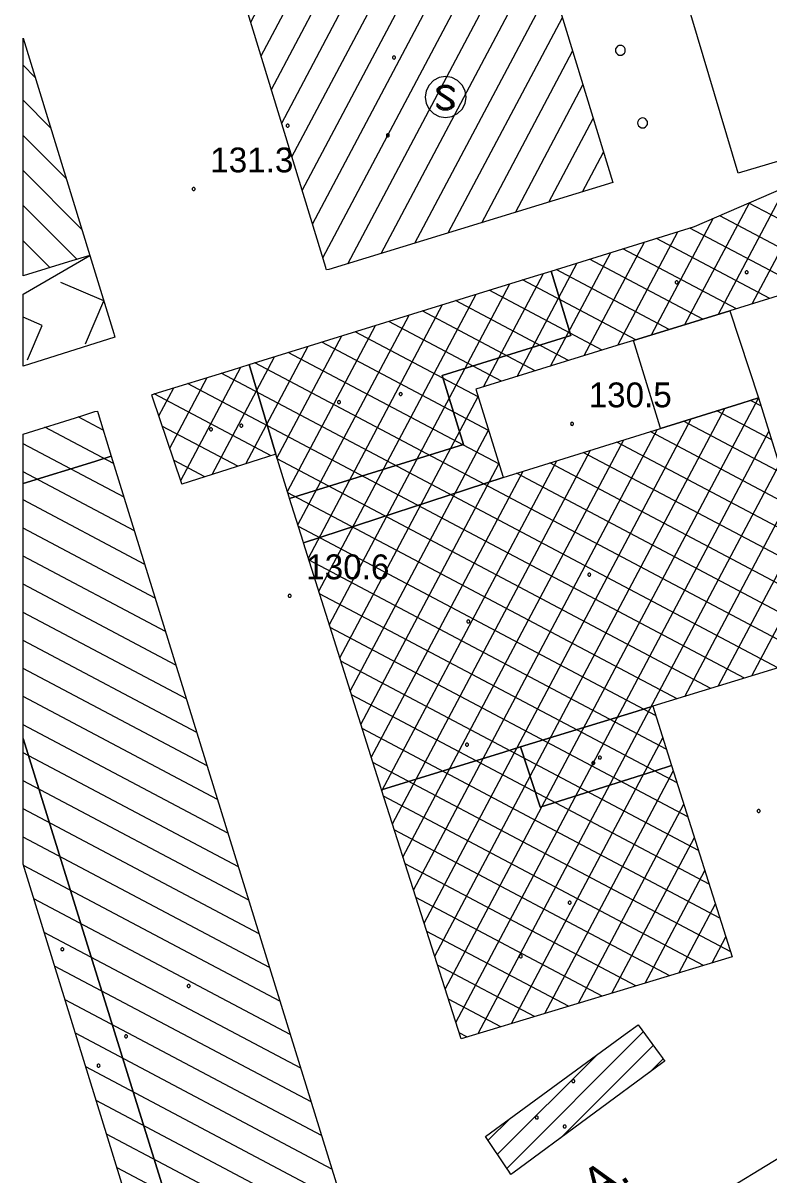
# Model space of a CAD drawing. Extents: x 513373 to 514978, y 5038576 to 5040180.
# Drawn here: x 513373 to 513418.1, y 5038650.3 to 5038719.9 of the extents above; entities that cross this region are included whole.
import ezdxf

# ---------------------------------------------------------------- set-up
doc = ezdxf.new("R2010")
doc.units = 0
for name, color, linetype in [('2010300', 7, 'Continuous'), ('3030201', 7, 'Continuous'), ('3060104', 7, 'Continuous'), ('3090300', 7, 'Continuous'), ('C1131', 7, 'Continuous'), ('C12211', 7, 'Continuous'), ('C1228', 7, 'Continuous'), ('C211113', 7, 'Continuous'), ('C21159', 7, 'Continuous'), ('C21195', 7, 'Continuous'), ('CAMP_C12211', 7, 'Continuous'), ('CAMP_C1228', 7, 'Continuous'), ('CAMP_C21195', 7, 'Continuous'), ('Default', 7, 'Continuous'), ('F12107', 7, 'Continuous'), ('F12131', 7, 'Continuous'), ('F12132', 7, 'Continuous'), ('G4315', 7, 'Continuous'), ('TOP500', 7, 'Continuous'), ('TOP920', 7, 'Continuous')]:
    doc.layers.add(name, color=color, linetype=linetype)

# ---------------------------------------------------------------- blocks, each defined once
blk = doc.blocks.new('CAMP_3A5802B0')
at = {"layer": 'CAMP_C12211'}
for p, q in [((-2.527, 26.797), (-4.04, 27.598)), ((-1.899, 24.767), (-6.054, 26.968)), ((-1.271, 22.738), (-7.369, 25.967)), ((-0.644, 20.708), (-7.369, 24.269)), ((-0.016, 18.679), (-7.369, 22.572)), ((0.612, 16.649), (-7.369, 20.875)), ((1.24, 14.619), (-7.369, 19.177)), ((1.867, 12.59), (-7.369, 17.48)), ((2.495, 10.56), (-7.369, 15.783)), ((3.123, 8.53), (-7.369, 14.086)), ((3.75, 6.501), (-7.369, 12.388)), ((4.378, 4.471), (-7.369, 10.691)), ((5.006, 2.441), (-7.369, 8.994)), ((5.634, 0.412), (-7.37, 7.297)), ((6.261, -1.618), (-7.37, 5.599)), ((6.889, -3.648), (-7.37, 3.902)), ((7.517, -5.677), (-7.37, 2.205)), ((8.144, -7.707), (-7.345, 0.494)), ((8.772, -9.736), (-6.717, -1.535)), ((9.4, -11.766), (-6.089, -3.565)), ((10.028, -13.796), (-5.461, -5.595)), ((10.655, -15.825), (-4.833, -7.625)), ((11.283, -17.855), (-4.206, -9.654)), ((11.911, -19.885), (-3.578, -11.684)), ((12.539, -21.914), (-2.95, -13.714)), ((11.923, -23.286), (-2.322, -15.743)), ((9.9, -23.912), (-1.695, -17.773)), ((7.876, -24.538), (-1.067, -19.803)), ((5.853, -25.164), (-0.439, -21.832)), ((3.829, -25.79), (0.188, -23.862)), ((1.806, -26.415), (0.816, -25.891))]:
    blk.add_line(p, q, dxfattribs=at)
blk = doc.blocks.new('CAMP_540BAC70')
at = {"layer": 'CAMP_C1228'}
for p, q in [((8.768, 14.056), (13.188, 22.405)), ((14.521, 22.096), (13.601, 22.584)), ((10.76, 14.613), (14.596, 21.858)), ((15.156, 20.063), (11.837, 21.82)), ((6.74, 13.431), (10.986, 21.452)), ((15.792, 18.029), (10.073, 21.057)), ((4.712, 12.807), (8.784, 20.499)), ((16.427, 15.996), (8.31, 20.293)), ((2.684, 12.182), (6.582, 19.545)), ((17.062, 13.962), (6.546, 19.53)), ((11.386, 12.589), (15.226, 19.842)), ((0.656, 11.558), (4.38, 18.592)), ((17.697, 11.928), (4.783, 18.766)), ((-1.372, 10.933), (2.262, 17.798)), ((9.846, 14.388), (2.984, 18.021)), ((12.011, 10.565), (15.855, 17.825)), ((-3.401, 10.307), (0.232, 17.168)), ((5.793, 13.14), (-1.06, 16.768)), ((7.819, 13.764), (0.962, 17.395)), ((-5.429, 9.682), (-1.799, 16.539)), ((3.766, 12.515), (-3.081, 16.141)), ((-7.457, 9.057), (-3.829, 15.909)), ((1.739, 11.891), (-5.103, 15.514)), ((12.637, 8.541), (16.485, 15.809)), ((-18.794, -5.942), (-7.891, 14.65)), ((-9.486, 8.432), (-5.86, 15.279)), ((-0.288, 11.267), (-7.125, 14.887)), ((-19.426, -3.932), (-9.921, 14.02)), ((-2.314, 10.643), (-9.146, 14.26)), ((-20.059, -1.922), (-11.952, 13.39)), ((-4.34, 10.018), (-11.168, 13.633)), ((18.332, 9.895), (11.022, 13.765)), ((13.263, 6.518), (17.115, 13.793)), ((-20.692, 0.089), (-13.983, 12.761)), ((-6.366, 9.393), (-13.19, 13.007)), ((-21.325, 2.099), (-16.014, 12.131)), ((-8.392, 8.769), (-15.211, 12.38)), ((-21.958, 4.109), (-18.044, 11.501)), ((-9.799, 7.817), (-17.233, 11.753)), ((18.967, 7.861), (11.649, 11.736)), ((13.889, 4.494), (17.745, 11.777)), ((-23.83, 3.779), (-20.075, 10.872)), ((-8.55, 3.761), (-21.276, 10.499)), ((-9.175, 5.789), (-19.255, 11.126)), ((-25.872, 3.129), (-22.106, 10.242)), ((10.329, -7.932), (-23.298, 9.872)), ((14.514, 2.47), (18.374, 9.76)), ((-27.767, 2.755), (-24.136, 9.614)), ((8.3, -8.556), (-25.324, 9.248)), ((19.603, 5.828), (12.277, 9.706)), ((-29.088, 6.671), (-28.191, 8.365)), ((-28.427, 4.713), (-26.163, 8.989)), ((6.272, -9.179), (-27.351, 8.624)), ((-22.316, 4.261), (-29.378, 8)), ((-18.161, -7.952), (-9.804, 7.831)), ((-11.793, -27.982), (7.121, 7.74)), ((20.238, 3.794), (12.904, 7.677)), ((15.14, 0.446), (19.004, 7.744)), ((-12.432, -25.984), (5.096, 7.121)), ((7.9, 5.235), (4.618, 6.972)), ((7.268, 7.267), (6.637, 7.6)), ((-13.072, -23.986), (3.064, 6.489)), ((8.531, 3.203), (2.598, 6.344)), ((-24.319, 3.623), (-28.873, 6.035)), ((-17.528, -9.962), (-9.179, 5.805)), ((-13.711, -21.987), (1.032, 5.857)), ((-11.154, -29.981), (7.749, 5.72)), ((9.163, 1.171), (0.579, 5.716)), ((20.873, 1.76), (13.532, 5.647)), ((15.766, -1.577), (19.634, 5.728)), ((-14.35, -19.989), (-1, 5.225)), ((9.795, -0.86), (-1.441, 5.088)), ((-14.989, -17.991), (-3.031, 4.594)), ((10.427, -2.892), (-3.46, 4.46)), ((-26.321, 2.986), (-28.176, 3.969)), ((4.244, -9.802), (-21.944, 4.063)), ((-16.895, -11.973), (-8.555, 3.778)), ((-15.629, -15.993), (-5.063, 3.962)), ((-9.815, -30.657), (8.377, 3.701)), ((11.058, -4.924), (-5.48, 3.832)), ((21.508, -0.273), (14.159, 3.618)), ((16.392, -3.601), (20.264, 3.712)), ((-16.262, -13.983), (-7.095, 3.33)), ((11.69, -6.956), (-7.499, 3.204)), ((2.215, -10.426), (-21.303, 2.027)), ((2.668, -10.286), (9.005, 1.681)), ((22.143, -2.307), (14.787, 1.588)), ((17.017, -5.625), (20.893, 1.696)), ((0.908, -11.431), (-20.661, -0.01)), ((4.695, -9.664), (9.633, -0.339)), ((22.779, -4.34), (15.415, -0.441)), ((17.643, -7.649), (21.523, -0.321)), ((1.557, -13.471), (-20.02, -2.047)), ((6.722, -9.041), (10.26, -2.358)), ((23.414, -6.374), (16.042, -2.471)), ((18.269, -9.672), (22.153, -2.337)), ((2.205, -15.512), (-19.379, -4.084)), ((8.75, -8.418), (10.888, -4.378)), ((23.709, -8.227), (16.67, -4.5)), ((20.138, -9.347), (22.783, -4.353)), ((2.853, -17.552), (-18.737, -6.121)), ((10.777, -7.795), (11.516, -6.397)), ((21.695, -8.859), (17.297, -6.53)), ((22.174, -8.709), (23.412, -6.369)), ((3.501, -19.593), (-18.096, -8.158)), ((19.682, -9.49), (17.925, -8.56)), ((4.15, -21.633), (-17.455, -10.195)), ((4.798, -23.674), (-16.813, -12.231)), ((-7.794, -30.047), (1.341, -12.793)), ((5.446, -25.714), (-16.172, -14.268)), ((-5.774, -29.437), (1.978, -14.796)), ((3.808, -26.544), (-15.528, -16.306)), ((-3.754, -28.827), (2.614, -16.8)), ((1.766, -27.16), (-14.875, -18.35)), ((-1.734, -28.217), (3.251, -18.803)), ((-0.276, -27.777), (-14.221, -20.393)), ((0.286, -27.607), (3.887, -20.807)), ((-2.317, -28.393), (-13.567, -22.436)), ((2.307, -26.997), (4.524, -22.81)), ((-4.359, -29.009), (-12.914, -24.48)), ((4.327, -26.387), (5.16, -24.814)), ((-6.4, -29.626), (-12.26, -26.523)), ((-8.442, -30.242), (-11.606, -28.567)), ((-10.483, -30.859), (-10.953, -30.61))]:
    blk.add_line(p, q, dxfattribs=at)
blk = doc.blocks.new('CAMP_E6EC42B5')
at = {"layer": 'CAMP_C12211'}
for p, q in [((-0.396, 5.699), (-1.115, 6.418)), ((0.543, 2.639), (-1.115, 4.297)), ((1.482, -0.422), (-1.115, 2.176)), ((2.421, -3.482), (-1.115, 0.054)), ((2.131, -5.313), (-1.115, -2.067)), ((0.508, -5.811), (-1.115, -4.188))]:
    blk.add_line(p, q, dxfattribs=at)
blk = doc.blocks.new('CAMP_7295D72C')
at = {"layer": 'CAMP_C12211'}
for p, q in [((15.402, 5.835), (27.505, 28.695)), ((11.114, 0.944), (25.534, 28.177)), ((9.09, 0.327), (23.51, 27.56)), ((7.067, -0.29), (21.486, 26.943)), ((17.426, 6.452), (28.125, 26.661)), ((15.419, 18.691), (19.462, 26.326)), ((14.179, 22.76), (15.414, 25.093)), ((14.799, 20.725), (17.438, 25.71)), ((18.998, 6.217), (28.745, 24.626)), ((19.619, 4.183), (29.366, 22.592)), ((20.239, 2.149), (29.986, 20.557)), ((20.992, 0.365), (30.606, 18.523)), ((5.043, -0.907), (14.588, 17.121)), ((3.019, -1.524), (12.564, 16.504)), ((23.016, 0.982), (31.226, 16.488)), ((1.275, -1.612), (10.54, 15.887)), ((-17.372, -7.98), (-5.338, 14.749)), ((-0.945, 0.606), (6.492, 14.653)), ((0.651, 0.415), (8.516, 15.27)), ((-19.388, -8.582), (-7.363, 14.13)), ((-15.356, -7.378), (-3.717, 14.606)), ((-2.961, 0.006), (4.468, 14.036)), ((25.04, 1.599), (31.846, 14.454)), ((-21.404, -9.183), (-9.388, 13.51)), ((-16.459, -22.283), (2.444, 13.419)), ((-23.42, -9.785), (-11.414, 12.891)), ((-13.562, -7.195), (-3.094, 12.575)), ((-12.321, -11.262), (0.42, 12.802)), ((-24.597, -8.802), (-13.439, 12.272)), ((-12.941, -9.228), (-1.603, 12.185)), ((27.064, 2.216), (32.466, 12.419)), ((-25.249, -6.828), (-15.464, 11.652)), ((-27.268, -7.437), (-17.489, 11.033)), ((-31.307, -8.654), (-21.54, 9.794)), ((-29.288, -8.045), (-19.515, 10.413)), ((29.088, 2.833), (33.086, 10.385)), ((-27.723, 1.321), (-23.565, 9.175)), ((-28.349, 3.345), (-25.59, 8.555)), ((-28.974, 5.369), (-27.615, 7.936)), ((31.112, 3.45), (33.706, 8.35)), ((33.136, 4.067), (34.326, 6.316)), ((13.138, 1.561), (14.823, 4.742)), ((15.162, 2.178), (15.443, 2.708)), ((-32.079, -6.906), (-28.195, 0.43)), ((-32.079, -3.7), (-30.208, -0.167)), ((-5.249, -4.317), (-3.742, -1.471)), ((-3.237, -3.721), (-3.133, -3.526)), ((-15.838, -24.317), (-6.237, -6.182)), ((-15.218, -26.35), (-5.616, -8.215)), ((-14.597, -28.383), (-4.995, -10.248)), ((-17.08, -20.25), (-12.345, -11.308)), ((-17.701, -18.217), (-14.376, -11.939)), ((-13.976, -30.416), (-4.374, -12.281)), ((-12.474, -30.784), (-2.542, -12.026)), ((-10.448, -30.164), (-0.748, -11.844)), ((-18.943, -14.151), (-18.439, -13.2)), ((-18.322, -16.184), (-16.408, -12.569)), ((-8.422, -29.543), (-0.127, -13.877)), ((-6.396, -28.923), (0.494, -15.91)), ((-4.37, -28.302), (1.114, -17.943)), ((-2.345, -27.682), (1.735, -19.976)), ((-0.319, -27.061), (2.356, -22.009)), ((1.707, -26.441), (2.977, -24.043))]:
    blk.add_line(p, q, dxfattribs=at)
blk = doc.blocks.new('CAMP_DF5335D6')
at = {"layer": 'CAMP_C21195'}
for p, q in [((-4.236, -4.236), (4.007, 4.007)), ((-0.991, -2.405), (4.607, 3.193)), ((-4.803, -3.389), (1.235, 2.649)), ((4.389, 1.561), (5.206, 2.378)), ((-5.37, -2.542), (-4.044, -1.215))]:
    blk.add_line(p, q, dxfattribs=at)
blk = doc.blocks.new('08020400')
at = {"layer": 'Default'}
for p, q in [((-0.086, 0.028), (-0.09, 0)), ((-0.09, 0), (-0.086, -0.028)), ((-0.073, 0.053), (-0.086, 0.028)), ((-0.053, 0.073), (-0.073, 0.053)), ((-0.028, 0.086), (-0.053, 0.073)), ((0, 0.09), (-0.028, 0.086)), ((0.028, 0.086), (0, 0.09)), ((0.053, 0.073), (0.028, 0.086)), ((0.073, 0.053), (0.053, 0.073)), ((0.086, 0.028), (0.073, 0.053)), ((0.09, 0), (0.086, 0.028)), ((0.086, -0.028), (0.09, 0)), ((-0.086, -0.028), (-0.073, -0.053)), ((-0.073, -0.053), (-0.053, -0.073)), ((-0.053, -0.073), (-0.028, -0.086)), ((-0.028, -0.086), (0, -0.09)), ((0, -0.09), (0.028, -0.086)), ((0.028, -0.086), (0.053, -0.073)), ((0.053, -0.073), (0.073, -0.053)), ((0.073, -0.053), (0.086, -0.028))]:
    blk.add_line(p, q, dxfattribs=at)
blk = doc.blocks.new('NSIMB25')
at = {"layer": 'Default'}
for p, q in [((-0.086, 0.028), (-0.09, 0)), ((-0.09, 0), (-0.086, -0.028)), ((-0.073, 0.053), (-0.086, 0.028)), ((-0.053, 0.073), (-0.073, 0.053)), ((-0.028, 0.086), (-0.053, 0.073)), ((0, 0.09), (-0.028, 0.086)), ((0.028, 0.086), (0, 0.09)), ((0.053, 0.073), (0.028, 0.086)), ((0.073, 0.053), (0.053, 0.073)), ((0.086, 0.028), (0.073, 0.053)), ((0.09, 0), (0.086, 0.028)), ((0.086, -0.028), (0.09, 0)), ((-0.086, -0.028), (-0.073, -0.053)), ((-0.073, -0.053), (-0.053, -0.073)), ((-0.053, -0.073), (-0.028, -0.086)), ((-0.028, -0.086), (0, -0.09)), ((0, -0.09), (0.028, -0.086)), ((0.028, -0.086), (0.053, -0.073)), ((0.053, -0.073), (0.073, -0.053)), ((0.073, -0.053), (0.086, -0.028))]:
    blk.add_line(p, q, dxfattribs=at)
blk = doc.blocks.new('05010100')
at = {"layer": 'Default'}
for p, q in [((-0.143, 0.046), (-0.15, 0)), ((-0.15, 0), (-0.143, -0.046)), ((-0.121, 0.088), (-0.143, 0.046)), ((-0.088, 0.121), (-0.121, 0.088)), ((-0.046, 0.143), (-0.088, 0.121)), ((0, 0.15), (-0.046, 0.143)), ((0.046, 0.143), (0, 0.15)), ((0.088, 0.121), (0.046, 0.143)), ((0.121, 0.088), (0.088, 0.121)), ((0.143, 0.046), (0.121, 0.088)), ((0.15, 0), (0.143, 0.046)), ((0.143, -0.046), (0.15, 0)), ((-0.143, -0.046), (-0.121, -0.088)), ((-0.121, -0.088), (-0.088, -0.121)), ((-0.088, -0.121), (-0.046, -0.143)), ((-0.046, -0.143), (0, -0.15)), ((0, -0.15), (0.046, -0.143)), ((0.046, -0.143), (0.088, -0.121)), ((0.088, -0.121), (0.121, -0.088)), ((0.121, -0.088), (0.143, -0.046))]:
    blk.add_line(p, q, dxfattribs=at)
blk = doc.blocks.new('03030201')
at = {"layer": 'Default'}
for p, q in [((-1.001, 0.728), (-1.177, 0.382)), ((-0.728, 1.001), (-1.001, 0.728)), ((-0.382, 1.177), (-0.728, 1.001)), ((0, 1.237), (-0.382, 1.177)), ((-0.368, 0.643), (-0.158, 0.718)), ((-0.158, 0.718), (0.127, 0.718)), ((0.382, 1.177), (0, 1.237)), ((0.127, 0.718), (0.337, 0.643)), ((0.728, 1.001), (0.382, 1.177)), ((1.001, 0.728), (0.728, 1.001)), ((1.177, 0.382), (1.001, 0.728)), ((-1.177, 0.382), (-1.238, 0)), ((-1.238, 0), (-1.177, -0.382)), ((-0.518, 0.508), (-0.368, 0.643)), ((-0.518, 0.358), (-0.518, 0.508)), ((-0.443, 0.223), (-0.518, 0.358)), ((-0.333, 0.584), (-0.451, 0.478)), ((-0.451, 0.478), (-0.451, 0.376)), ((-0.451, 0.376), (-0.389, 0.265)), ((-0.368, 0.148), (-0.443, 0.223)), ((-0.389, 0.265), (-0.326, 0.201)), ((-0.298, 0.526), (-0.383, 0.448)), ((-0.383, 0.448), (-0.383, 0.394)), ((-0.383, 0.394), (-0.335, 0.306)), ((0.148, -0.186), (-0.368, 0.148)), ((-0.335, 0.306), (-0.287, 0.257)), ((-0.147, 0.651), (-0.333, 0.584)), ((-0.326, 0.201), (0.183, -0.128)), ((-0.135, 0.583), (-0.298, 0.526)), ((-0.287, 0.257), (-0.18, 0.198)), ((-0.18, 0.198), (0.337, -0.137)), ((0.115, 0.651), (-0.147, 0.651)), ((0.103, 0.583), (-0.135, 0.583)), ((0.266, 0.526), (0.103, 0.583)), ((0.301, 0.584), (0.115, 0.651)), ((0.487, 0.327), (0.266, 0.526)), ((0.487, 0.418), (0.301, 0.584)), ((0.337, 0.643), (0.487, 0.508)), ((0.487, 0.508), (0.487, 0.327)), ((1.238, 0), (1.177, 0.382)), ((1.177, -0.382), (1.238, 0)), ((-1.177, -0.382), (-1.001, -0.728)), ((-0.518, -0.39), (-0.298, -0.588)), ((-0.518, -0.572), (-0.518, -0.39)), ((-0.333, -0.647), (-0.518, -0.481)), ((-0.368, -0.707), (-0.518, -0.572)), ((-0.147, -0.714), (-0.333, -0.647)), ((-0.298, -0.588), (-0.135, -0.647)), ((-0.135, -0.647), (0.103, -0.647)), ((0.103, -0.647), (0.266, -0.588)), ((0.301, -0.647), (0.115, -0.714)), ((0.254, -0.245), (0.148, -0.186)), ((0.183, -0.128), (0.295, -0.191)), ((0.302, -0.293), (0.254, -0.245)), ((0.266, -0.588), (0.352, -0.512)), ((0.295, -0.191), (0.357, -0.253)), ((0.419, -0.542), (0.301, -0.647)), ((0.352, -0.382), (0.302, -0.293)), ((0.337, -0.137), (0.412, -0.212)), ((0.487, -0.572), (0.337, -0.707)), ((0.352, -0.512), (0.352, -0.382)), ((0.357, -0.253), (0.419, -0.364)), ((0.412, -0.212), (0.487, -0.347)), ((0.419, -0.364), (0.419, -0.542)), ((0.487, -0.347), (0.487, -0.572)), ((1.001, -0.728), (1.177, -0.382)), ((-1.001, -0.728), (-0.728, -1.001)), ((-0.728, -1.001), (-0.382, -1.177)), ((-0.382, -1.177), (0, -1.238)), ((-0.158, -0.782), (-0.368, -0.707)), ((0.127, -0.782), (-0.158, -0.782)), ((0.115, -0.714), (-0.147, -0.714)), ((0, -1.238), (0.382, -1.177)), ((0.337, -0.707), (0.127, -0.782)), ((0.382, -1.177), (0.728, -1.001)), ((0.728, -1.001), (1.001, -0.728))]:
    blk.add_line(p, q, dxfattribs=at)
blk = doc.blocks.new('A$C3704598A')
at = {"layer": '2010300'}
blk.add_lwpolyline([(63.875, -708.514), (65.701, -714.881), (66.154, -716.461), (50.099, -726.135), (45.283, -729.066), (39.595, -732.528), (29.764, -739.427), (17.578, -748.279), (17.196, -748.707), (8.795, -758.134), (8.774, -758.179), (8.768, -758.22), (8.774, -758.259)], dxfattribs=at)
at = {"layer": '3060104'}
blk.add_lwpolyline([(46.493, -648.911), (51.804, -666.759), (43.181, -669.324), (37.87, -651.477), (46.493, -648.911)], dxfattribs=at)
at = {"layer": '3090300'}
for points in [[(4.866, -677.035), (2.264, -675.925)], [(3.756, -679.637), (4.866, -677.035)], [(1.154, -678.525), (-0.009, -678.027)], [(0.264, -680.607), (1.154, -678.525)]]:
    blk.add_lwpolyline(points, dxfattribs=at)
at = {"layer": 'C1131'}
for points in [[(18.467, -675.14), (18.321, -675.169), (18.306, -675.118), (18.278, -675.026), (12.906, -657.436), (19.76, -655.307), (18.41, -650.882), (22.191, -649.727), (24.391, -649.056), (25.393, -648.75), (26.501, -652.377), (27.429, -655.415), (27.762, -656.505), (27.781, -656.57), (30.219, -655.825), (31.22, -655.519), (35.608, -669.89)], [(4.016, -674.287), (2.735, -674.68), (-0.009, -675.522), (-0.009, -661.169)], [(51.614, -667.946), (53.547, -674.136), (52.554, -674.469), (48.027, -675.988), (47.026, -676.297), (42.681, -677.635), (36.859, -679.428), (35.859, -679.737), (27.338, -682.363), (28.96, -687.628), (28.982, -687.698), (16.933, -691.651), (16.906, -691.566), (16.089, -688.971), (26.59, -685.714), (25.297, -681.545), (33.069, -679.135), (31.883, -675.231), (40.543, -672.546), (50.595, -668.195), (50.678, -668.159), (51.424, -667.836), (51.569, -667.804), (51.589, -667.868)], [(16.089, -688.971), (16.067, -688.902), (15.249, -686.303), (13.644, -680.887), (30.883, -675.541), (31.883, -675.231), (33.069, -679.135), (25.297, -681.545), (26.59, -685.714)], [(15.249, -686.303), (14.252, -686.62), (9.586, -688.105), (9.561, -688.029), (7.814, -682.851), (7.769, -682.709), (7.907, -682.653), (12.643, -681.195), (13.644, -680.887)], [(38.017, -701.534), (37.017, -701.842), (30.026, -703.99), (29.027, -704.297), (21.631, -706.571), (21.61, -706.504), (16.933, -691.651), (28.982, -687.698), (38.488, -684.742), (43.402, -683.214), (44.401, -682.903), (49.132, -698.118)], [(4.503, -683.775), (4.521, -683.833), (5.322, -686.422), (4.323, -686.733), (-0.009, -688.08), (-0.009, -685.083), (3.475, -683.992), (4.332, -683.724), (4.477, -683.691)], [(19.345, -731.764), (18.346, -732.072), (9.716, -734.736), (9.695, -734.668), (-0.009, -703.475), (-0.009, -688.08), (4.323, -686.733), (5.322, -686.422)], [(39.156, -705.118), (38.159, -705.434), (31.217, -707.63), (31.192, -707.555), (30.026, -703.99), (37.017, -701.842), (38.017, -701.534)], [(9.695, -734.668), (9.716, -734.736), (18.346, -732.072), (19.345, -731.764), (20.232, -734.631), (10.421, -737.666), (9.422, -737.975), (8.41, -738.288), (8.389, -738.219), (6.222, -731.209), (-0.009, -711.064), (-0.009, -703.475)], [(39.156, -705.118), (42.827, -716.673), (26.445, -721.619), (26.425, -721.557), (21.631, -706.571), (29.027, -704.297), (30.026, -703.99), (31.192, -707.555), (31.217, -707.63), (38.159, -705.434)], [(38.657, -722.847), (38.746, -722.968), (38.634, -723.066), (29.58, -729.741), (29.451, -729.815), (29.327, -729.629), (29.231, -729.486), (27.915, -727.52), (36.354, -721.343), (37.132, -720.773), (38.413, -722.515), (38.591, -722.757)]]:
    blk.add_lwpolyline(points, close=True, dxfattribs=at)
at = {"layer": 'C12211'}
blk.add_lwpolyline([(31.22, -655.519), (35.608, -669.89), (18.467, -675.14), (18.321, -675.169), (18.306, -675.118), (18.278, -675.026), (12.906, -657.436)], dxfattribs=at)
for points in [[(4.016, -674.287), (2.735, -674.68), (-0.009, -675.522), (-0.009, -661.169)], [(4.503, -683.775), (4.521, -683.833), (5.322, -686.422), (19.345, -731.764), (20.232, -734.631), (10.421, -737.666), (9.422, -737.975), (8.41, -738.288), (8.389, -738.219), (6.222, -731.209), (-0.009, -711.064), (-0.009, -685.083), (3.475, -683.992), (4.332, -683.724), (4.477, -683.691)]]:
    blk.add_lwpolyline(points, close=True, dxfattribs=at)
at = {"layer": 'C1228'}
blk.add_lwpolyline([(47.026, -676.297), (42.681, -677.635), (36.859, -679.428), (35.859, -679.737), (27.338, -682.363), (28.96, -687.628), (28.982, -687.698), (38.488, -684.742), (43.402, -683.214), (44.401, -682.903), (49.132, -698.118), (38.017, -701.534), (39.156, -705.118), (42.827, -716.673), (26.445, -721.619), (26.425, -721.557), (21.631, -706.571), (21.61, -706.504), (16.933, -691.651), (16.906, -691.566), (16.089, -688.971), (16.067, -688.902), (15.249, -686.303), (14.252, -686.62), (9.586, -688.105), (9.561, -688.029), (7.814, -682.851), (7.769, -682.709), (7.907, -682.653), (12.643, -681.195), (13.644, -680.887), (30.883, -675.541), (31.883, -675.231), (40.543, -672.546), (50.595, -668.195)], dxfattribs=at)
at = {"layer": 'C211113'}
blk.add_lwpolyline([(36.859, -679.428), (42.681, -677.635), (44.401, -682.903), (43.402, -683.214), (38.488, -684.742), (38.466, -684.672)], close=True, dxfattribs=at)
at = {"layer": 'C21159'}
blk.add_lwpolyline([(5.476, -679.006), (5.499, -679.082), (5.543, -679.224), (-0.009, -680.986), (-0.009, -676.634), (4.016, -674.287)], close=True, dxfattribs=at)
at = {"layer": 'C21195'}
blk.add_lwpolyline([(38.657, -722.847), (38.746, -722.968), (38.634, -723.066), (29.58, -729.741), (29.451, -729.815), (29.327, -729.629), (29.231, -729.486), (27.915, -727.52), (36.354, -721.343), (37.132, -720.773), (38.413, -722.515), (38.591, -722.757)], close=True, dxfattribs=at)
at = {"layer": '3030201'}
blk.add_blockref('03030201', (25.511, -664.721), dxfattribs=at)
at = {"layer": 'CAMP_C12211'}
for name, p in [('CAMP_7295D72C', (32.07, -644.01)), ('CAMP_E6EC42B5', (1.106, -669.212)), ('CAMP_3A5802B0', (7.36, -711.639))]:
    blk.add_blockref(name, p, dxfattribs=at)
at = {"layer": 'CAMP_C1228'}
blk.add_blockref('CAMP_540BAC70', (37.283, -690.653), dxfattribs=at)
at = {"layer": 'CAMP_C21195'}
blk.add_blockref('CAMP_DF5335D6', (33.445, -725.217), dxfattribs=at)
at = {"layer": 'F12107'}
for p in [(10.298, -670.27), (33.15, -684.467), (16.095, -694.857), (44.418, -707.858)]:
    blk.add_blockref('08020400', p, dxfattribs=at)
at = {"layer": 'F12131'}
for p in [(22.022, -667.032), (43.69, -675.304), (22.797, -682.668), (13.179, -684.574), (34.185, -693.574), (34.827, -704.631), (2.36, -716.213), (30.053, -716.644), (31.019, -726.384)]:
    blk.add_blockref('NSIMB25', p, dxfattribs=at)
at = {"layer": 'F12132'}
for p in [(22.399, -662.33), (15.976, -666.443), (39.463, -675.919), (19.076, -683.154), (11.341, -684.794), (26.882, -696.408), (26.805, -703.852), (34.43, -704.96), (32.998, -713.396), (9.988, -718.433), (6.214, -721.476), (4.549, -723.25), (33.223, -724.183), (32.702, -726.924)]:
    blk.add_blockref('NSIMB25', p, dxfattribs=at)
at = {"layer": 'G4315', "xscale": 2, "yscale": 2}
for p in [(36.064, -661.895), (37.41, -666.284)]:
    blk.add_blockref('05010100', p, dxfattribs=at)
at = {"layer": 'TOP500'}
blk.add_text('A.', height=2, rotation=34.05122, dxfattribs=at).set_placement((34.665, -731.532))
at = {"layer": 'TOP920'}
for s, p in [('131.3', (11.298, -669.27)), ('130.5', (34.15, -683.467)), ('130.6', (17.095, -693.857))]:
    blk.add_text(s, height=1.5, dxfattribs=at).set_placement(p)

msp = doc.modelspace()

# ---------------------------------------------------------------- block references
at = {"layer": 'Default'}
msp.add_blockref('A$C3704598A', (513373.046, 5039380.14), dxfattribs=at)

doc.saveas('drawing.dxf')
